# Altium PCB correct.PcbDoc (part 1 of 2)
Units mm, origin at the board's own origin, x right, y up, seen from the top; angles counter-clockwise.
Board outline 184.4 x 190.25 mm, 2 copper layers (Top Layer, Bottom Layer); 180 components, 157 nets, 610 pads, 206 vias.
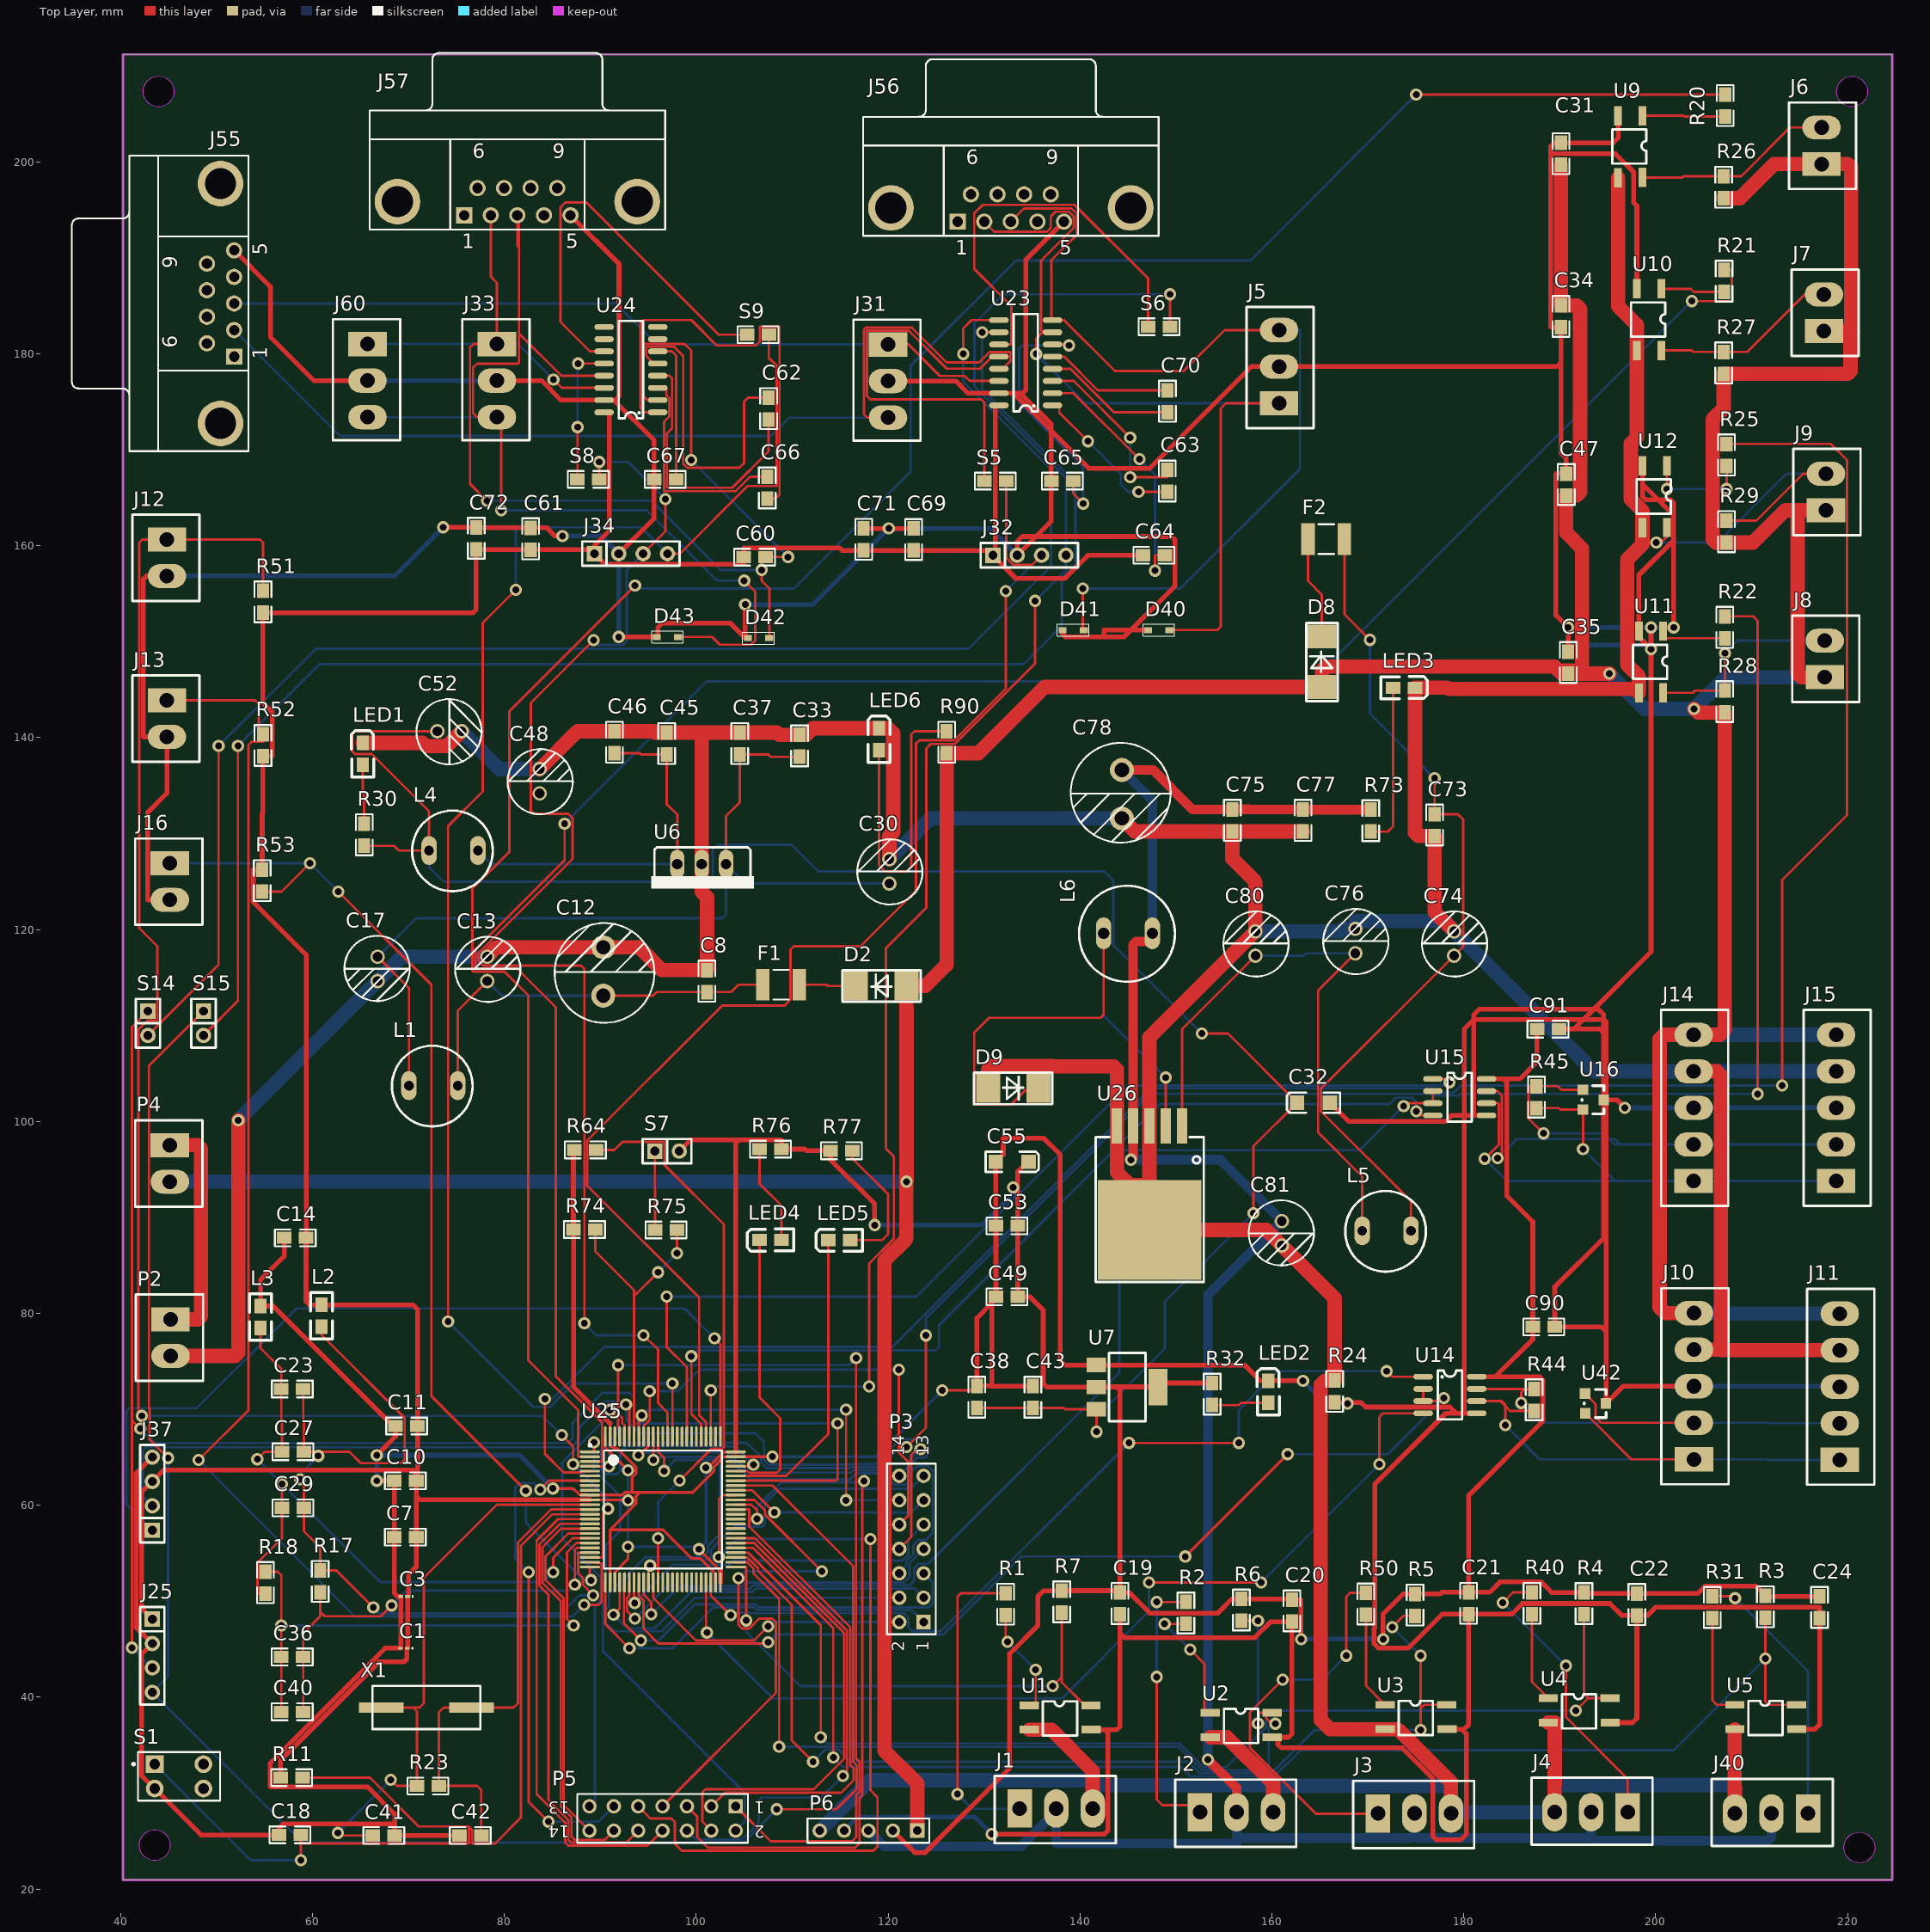
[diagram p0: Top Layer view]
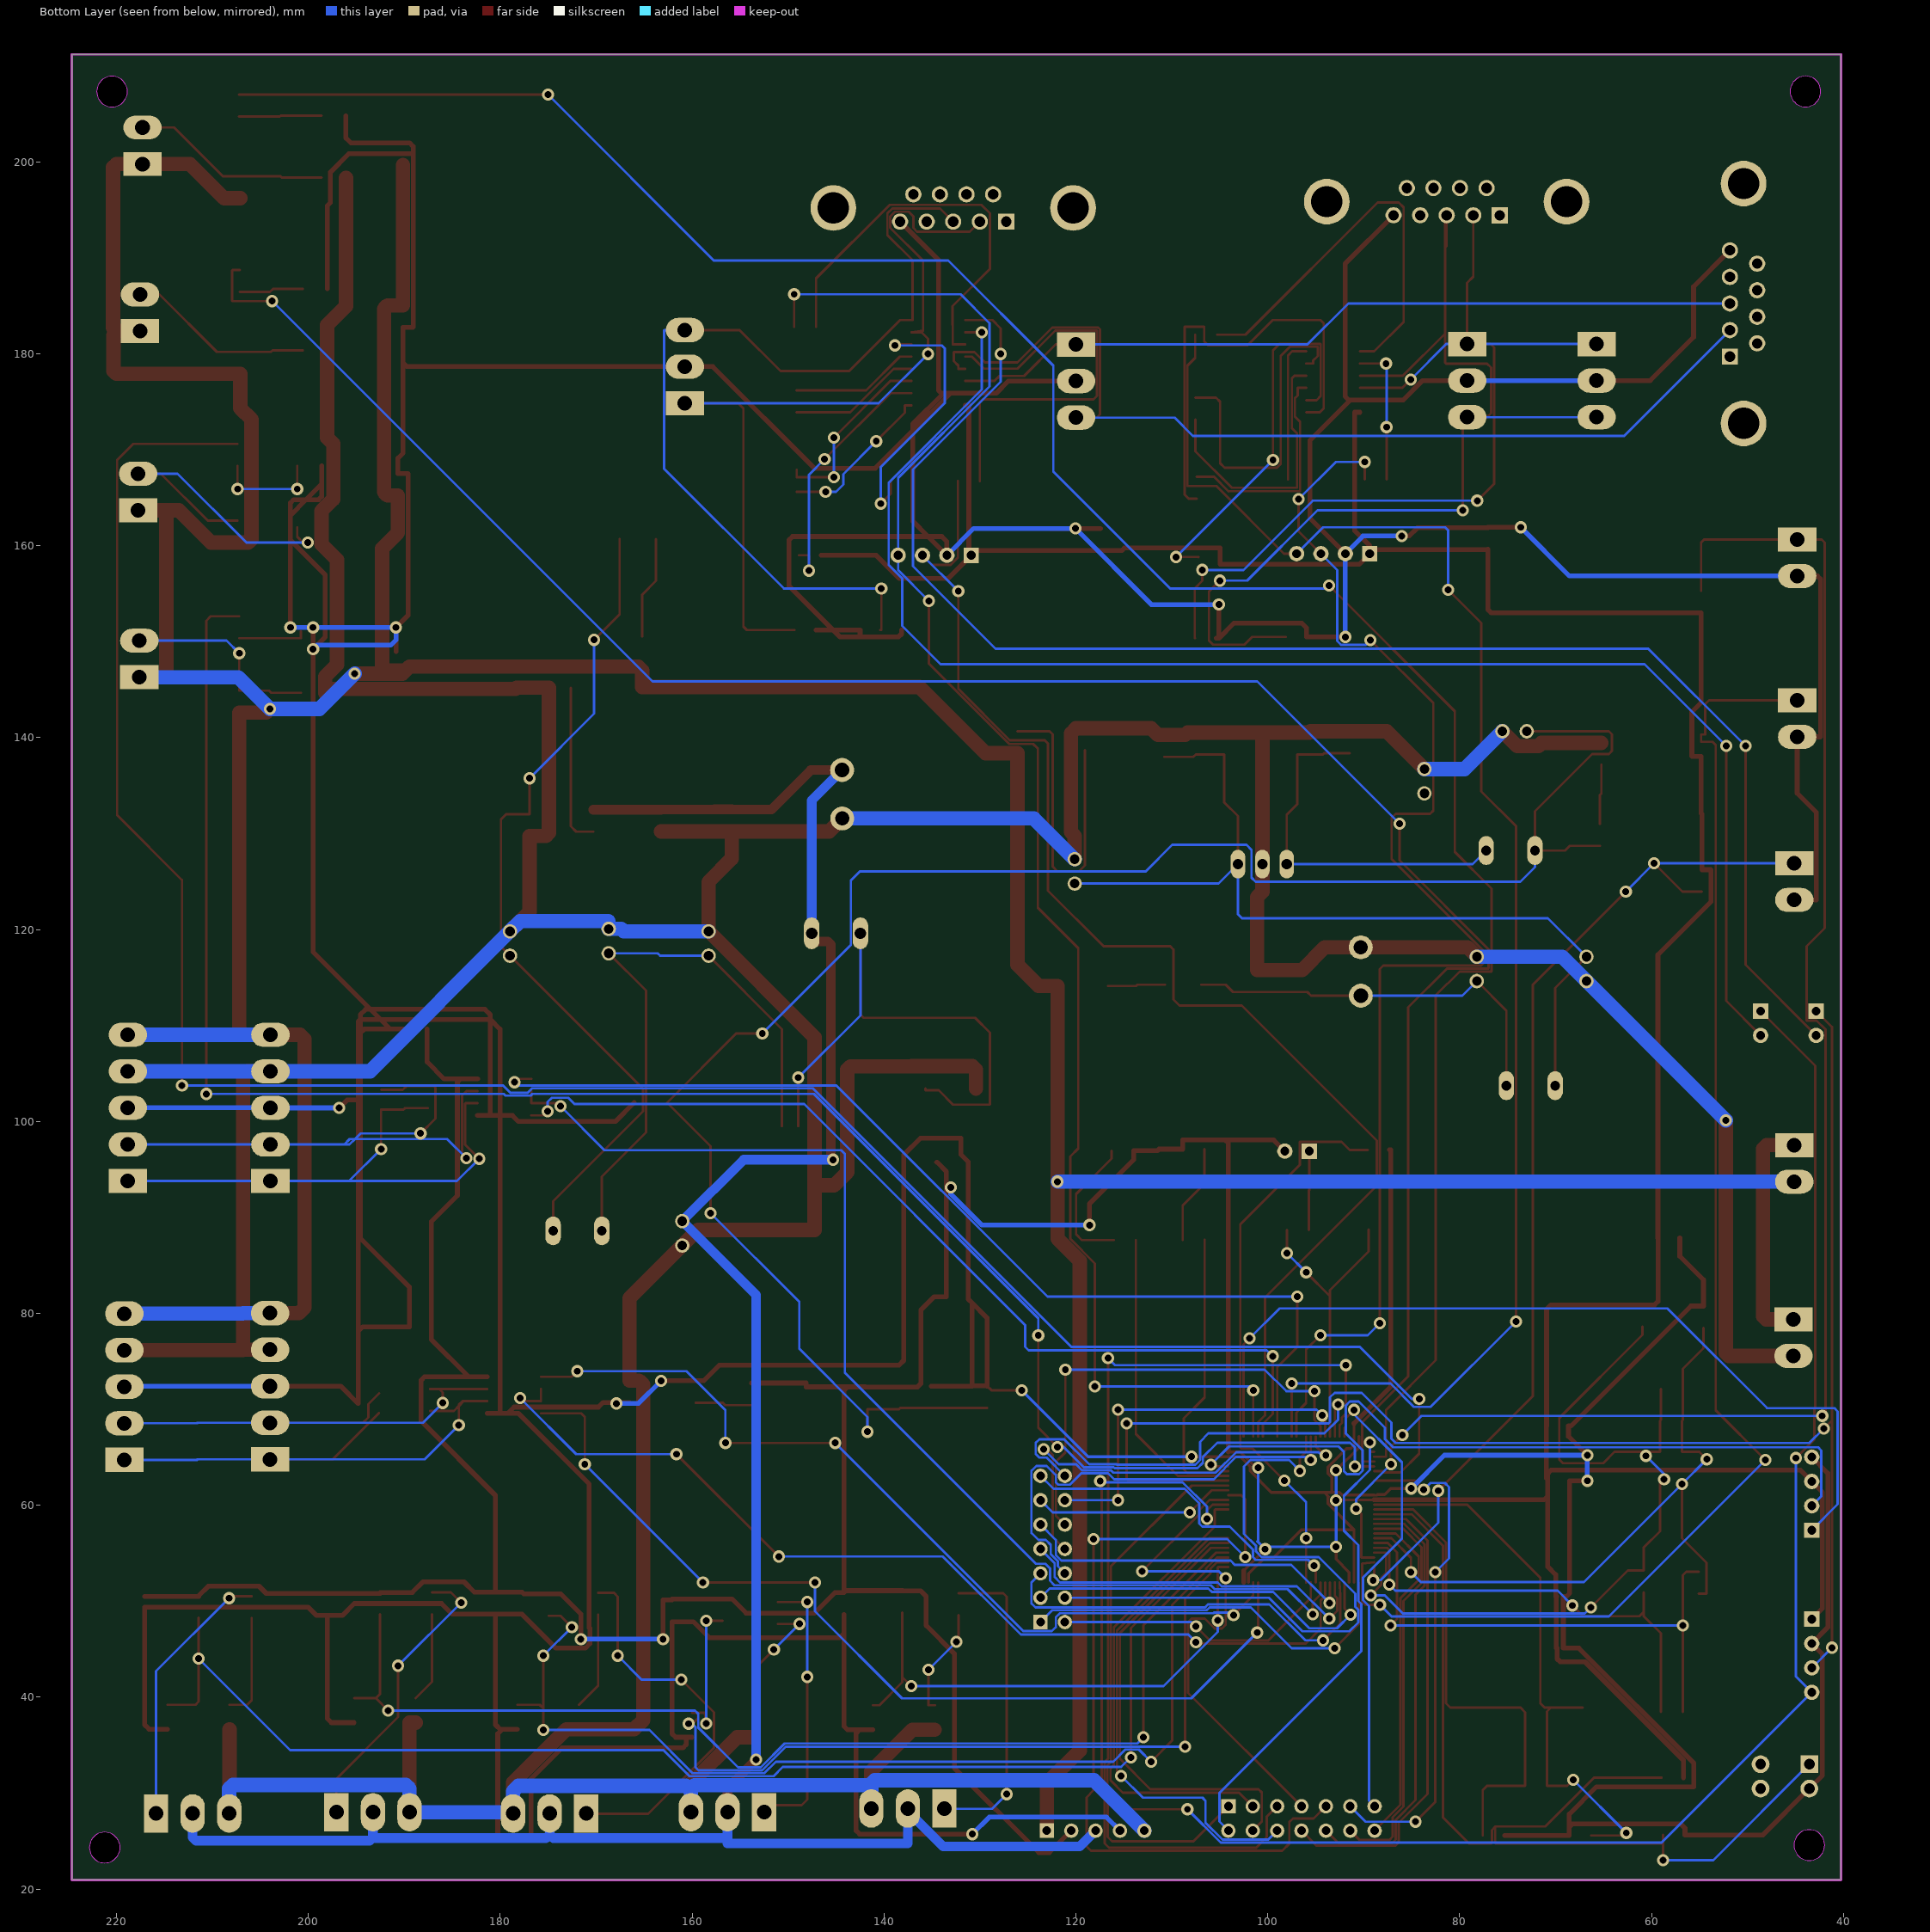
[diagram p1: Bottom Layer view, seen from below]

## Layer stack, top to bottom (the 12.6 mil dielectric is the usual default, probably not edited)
Top Solder: solder mask 0.0102, Solder Resist, Dk 3.5
Top Layer: signal copper 0.0356
Dielectric 1: dielectric 0.32, FR-4, Dk 4.8
Bottom Layer: signal copper 0.0356
Bottom Solder: solder mask 0.0102, Solder Resist, Dk 3.5

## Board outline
40.259,20.955 40.259,70.231 40.259,164.211 40.259,211.201 224.663,211.201 224.663,20.955
cut-out: 43.561,22.987 cw(c43.561,24.587) 41.961,24.587 cw(c43.561,24.587) 43.561,26.187 cw(c43.561,24.587) 45.161,24.587 cw(c43.561,24.587)
cut-out: 221.234,22.733 cw(c221.234,24.333) 219.634,24.333 cw(c221.234,24.333) 221.234,25.933 cw(c221.234,24.333) 222.834,24.333 cw(c221.234,24.333)
cut-out: 220.472,205.731 cw(c220.472,207.331) 218.872,207.331 cw(c220.472,207.331) 220.472,208.931 cw(c220.472,207.331) 222.072,207.331 cw(c220.472,207.331)
cut-out: 43.965,205.745 cw(c43.965,207.345) 42.365,207.345 cw(c43.965,207.345) 43.965,208.945 cw(c43.965,207.345) 45.565,207.345 cw(c43.965,207.345)

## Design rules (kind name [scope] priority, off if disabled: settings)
Clearance [All] p1: gap=0.051 ignorepadtopadclearanceinfootprint=FALSE except(0: Arc-Hole Track-Hole SMDPad-Hole THPad-Hole Via-Hole Fill-Hole Poly-Hole Region-Hole Text-Hole)
PolygonConnect [All] p1: connectstyle=Relief reliefconductorwidth=0.254 reliefentries=4 polygonreliefangle="90 Angle" airgapwidth=0.254
RoutingVias [All] p1: holewidth=0.711 width=1.27 viastyle="Through Hole" minholewidth=0.711 minwidth=1.27 maxholewidth=0.711 maxwidth=1.27
SolderMaskExpansion [All] p1: expansion=0.102
Width [All] p1: maxlimit=1.5 minlimit=0.254 preferedwidth=0.254 minimp=50.000000 maximp=50.000000 favimp=50.000000
30 further rules are at their usual default settings.

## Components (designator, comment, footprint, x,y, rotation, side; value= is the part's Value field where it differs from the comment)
C1 "10uf/50V 5%" 0603 69.523,45.103 r180 top
C3 "100nf/50V 5%" 0603 69.554,50.488 r180 top
C7 "100nf/50V 5%" 0805C 70.776,56.703 r180 top
C8 "100nf/50V 5%" 0805C 101.143,113.537 r90 top
C10 "100nf/50V 5%" 0805C 70.776,62.571 r180 top
C11 "100nf/50V 5%" 0805C 70.903,68.286 r180 top
C12 "220uf/35V" C10-35V330uf 90.312,113.108 r90 top
C13 "10uf/35V" C6.5-35V47uf 78.222,114.632 r90 top
C14 "100nf/50V 5%" 0805C 59.294,87.896 r180 top
C17 "220uf/35V" C6.5-35V47uf 66.792,117.172 r270 top
C18 "100nf/50V 5%" 0805C 56.571,25.63 r0 top
C19 "100nf/50V 5%" 0805C 144.19,48.683 r90 top
C20 "100nf/50V 5%" 0805C 162.115,47.915 r90 top
C21 "100nf/50V 5%" 0805C 180.53,48.7 r90 top
C22 "100nf/50V 5%" 0805C 198.056,48.573 r90 top
C23 "10uF/16V" 0805C 58.992,72.148 r180 top
C24 "100nf/50V 5%" 0805C 217.106,48.271 r90 top
C27 "100nf/50V 5%" 0805C 56.881,65.552 r0 top
C29 "10nf/50V 5%" 0805C 56.881,59.71 r0 top
C30 "47uf 50V" C6.5-35V47uf 120.132,124.792 r90 top
C31 "100nf/50V 5%" 0805C 190.119,201.938 r270 top
C32 "16V10uf" 1206-2 164.34,101.956 r180 top
C33 "100nf/50V 5%" 0805C 110.796,138.048 r90 top
C34 "100nf/50V 5%" 0805C 190.155,182.809 r90 top
C35 "100nf/50V 5%" 0805C 190.863,148.916 r270 top
C36 "10uf/50V 5%" 0805C 56.802,44.172 r0 top
C37 "10nf/50V 5%" 0805C 104.555,138.302 r90 top
C38 "100nf/50V 5%" 0805C 129.277,70.183 r90 top
C40 "10nf/50V 5%" 0805C 56.802,38.457 r0 top
C41 "20pF/50V 5%" 0805C 68.532,25.603 r180 top
C42 "20pF/50V 5%" 0805C 75.359,25.567 r0 top
C43 "10nf/50V 5%" 0805C 135.119,70.183 r90 top
C45 "10nf/50V 5%" 0805C 96.953,138.302 r90 top
C46 "100nf/50V 5%" 0805C 91.492,138.429 r90 top
C47 "100nf/50V 5%" 0805C 190.66,167.473 r270 top
C48 "47uf 50V" C6.5-35V47uf 83.683,134.19 r90 top
C49 "100nf/50V 5%" 0805C 133.468,81.74 r180 top
C52 "10uf 50V" C6.5-35V47uf 73.015,140.667 r0 top
C53 "10nf/50V 5%" 0805C 133.468,89.15 r180 top
C55 "16V10uf" 1206-2 132.931,95.783 r0 top
C60 "100nf/50V 5%" 0805C 105.006,158.794 r0 top
C61 "10uf/50V 5%" 0805C 82.761,159.638 r90 top
C62 "100nf/50V 5%" 0805C 107.528,175.383 r270 top
C63 "100nf/50V 5%" 0805C 149.119,165.656 r90 top
C64 "100nf/50V 5%" 0805C 146.609,158.986 r0 top
C65 "100nf/50V 5%" 0805C 139.248,166.769 r180 top
C66 "100nf/50V 5%" 0805C 107.437,164.938 r90 top
C67 "100nf/50V 5%" 0805C 97.846,166.94 r180 top
C69 "10uf/50V 5%" 0805C 122.677,159.56 r90 top
C70 "100nf/50V 5%" 0805C 149.101,176.149 r270 top
C71 "100nf/50V 5%" 0805C 117.434,161.75 r270 top
C72 "100nf/50V 5%" 0805C 77.048,161.873 r270 top
C73 "100nf/50V 5%" 0805C 176.942,131.982 r270 top
C74 "10uf/35V" C6.5-35V47uf 178.992,117.275 r90 top
C75 "10nf/50V 5%" 0805C 155.86,132.467 r270 top
C76 "220uf/35V" C6.5-35V47uf 168.705,117.529 r90 top
C77 "100nf/50V 5%" 0805C 163.226,132.467 r270 top
C78 "470u/16V" C10-35V330uf 144.371,136.625 r270 top
C80 "10u/35V" C6.5-35V47uf 158.291,117.275 r90 top
C81 "100uf/16V" C6.5-35V47uf 161.038,89.614 r270 top
C90 "100nf/50V 5%" 0805C 189.438,78.623 r180 top
C91 "100nf/50V 5%" 0805C 189.867,109.644 r180 top
D2 "1N5822" SS34 117.166,113.683 r270 top
D8 "1N5822" SS34 164.774,150.028 r180 top
D9 "1N5822" SS34 135.174,103.882 r90 top
D40 "SD12C" SD12C 148.219,151.213 r0 top
D41 "SD12C" SD12C 139.296,151.213 r0 top
D42 "SD12C" SD12C 106.497,150.368 r0 top
D43 "SD12C" SD12C 97.005,150.495 r0 top
F1 "500mA" 1812 108.829,114.251 r180 top
F2 "500mA" 1812 165.668,160.696 r0 top
J1 "CON3" CON-3P-3.81 133.738,28.37 r0 top
J2 "CON3" CON-3P-3.81 152.534,27.989 r0 top
J3 "CON3" CON-3P-3.81 171.076,27.862 r0 top
J4 "CON3" CON-3P-3.81 197.06,28.04 r180 top
J5 "CON3" CON-3P-3.81 160.782,174.879 r90 top
J6 "红色" CON-2P-3.81 217.297,199.779 r90 top
J7 "绿色" CON-2P-3.81 217.551,182.38 r90 top
J8 "黄色" CON-2P-3.81 217.627,146.297 r90 top
J9 "蓝色" CON-2P-3.81 217.754,163.696 r90 top
J10 "Header 5" CON-5P-3.81 203.996,64.838 r90 top
J11 "Header 5" CON-5P-3.81 219.19,64.788 r90 top
J12 "蓝色按键" CON-2P-3.81 44.831,160.655 r270 top
J13 "绿色按键" CON-2P-3.81 44.831,143.891 r270 top
J14 "Header 5" CON-5P-3.81 203.962,93.845 r90 top
J15 "Header 5" CON-5P-3.81 218.821,93.845 r90 top
J16 "绿色按键" CON-2P-3.81 45.136,126.899 r270 top
J25 "TTL" SIP4 43.307,44.323 r270 top
J31 "CON3" CON-3P-3.81 119.967,180.95 r270 top
J32 "USART4" SIP4 134.724,159.004 r0 top
J33 "CON3" CON-3P-3.81 79.2,180.994 r270 top
J34 "USART4" SIP4 93.195,159.175 r0 top
J37 "SWD" SIP4 43.307,61.214 r90 top
J40 "CON3" CON-3P-3.81 215.856,27.913 r180 top
J55 "D Connector 9" DSUB1.385-2H9 40.919,185.244 r90 top
J56 "D Connector 9" DSUB1.385-2H9 132.793,204.699 r0 top
J57 "D Connector 9" DSUB1.385-2H9 81.358,205.359 r0 top
J60 "CON3" CON-3P-3.81 65.712,180.994 r270 top
L1 "Inductor" LC-8.2 75.102,103.713 r180 top value="10uH 2A"
L2 "10uH" 0805 60.945,79.75 r270 top
L3 "10uH" 0805 54.595,79.623 r270 top
L4 "10uH 2A" LC-8.2 77.206,128.221 r180 top
L5 "Inductor" LC-8.2 174.466,88.581 r180 top value="10uH 2A"
L6 "331" LC-10 145.429,119.336 r180 top
LED1 "LED R" 0805D 65.268,137.238 r90 top
LED2 "LED B" 0805D 159.654,70.77 r90 top
LED3 "LED G" 0805D 172.727,145.178 r0 top
LED4 "LED R" 0805D 108.796,87.681 r180 top
LED5 "LED B" 0805D 115.965,87.657 r180 top
LED6 "LED B" 0805D 119.093,138.762 r90 top
P2 "Power24V" CON-2P-3.81 45.212,79.375 r270 top
P3 "Header 7X2" HDR2X7 123.701,47.829 r90 top
P4 "Power24V" CON-2P-3.81 45.136,97.536 r270 top
P5 "Header 7X2" HDR2X7 104.111,28.633 r180 top
P6 "Header 5" HDR1X5 123.034,26.093 r180 top
R1 "620R 1%" 0805R 132.295,48.579 r90 top
R2 "620R 1%" 0805R 151.091,47.659 r90 top
R3 "2K 1%" 0805R 211.479,48.307 r90 top
R4 "2K 1%" 0805R 192.577,48.652 r90 top
R5 "2K 1%" 0805R 174.967,48.5 r90 top
R6 "2K 1%" 0805R 156.869,47.977 r90 top
R7 "2K 1%" 0805R 138.137,48.833 r90 top
R11 "10k 1%" 0805R 58.938,31.66 r180 top
R17 "10R" 0805R 60.861,50.944 r90 top
R18 "10R" 0805R 55.06,53.057 r270 top
R20 "620R 1%" 0805R 207.289,204.755 r90 top
R21 "620R 1%" 0805R 207.18,186.467 r90 top
R22 "620R 1%" 0805R 207.256,150.384 r90 top
R23 "1M" 0805R 73.152,30.792 r180 top
R24 "0R 1%" 0805R 166.499,72.977 r270 top
R25 "620R 1%" 0805R 207.434,168.35 r90 top
R26 "2K 1%" 0805R 207.137,196.246 r90 top
R27 "2K 1%" 0805R 207.137,177.935 r90 top
R28 "2K 1%" 0805R 207.256,142.637 r90 top
R29 "2K 1%" 0805R 207.434,160.349 r90 top
R30 "10k 1%" 0805R 65.352,130.992 r270 top
R31 "620R 1%" 0805R 205.955,48.246 r90 top
R32 "10K 1%" 0805R 153.831,70.46 r90 top
R40 "620R 1%" 0805R 187.159,48.675 r90 top
R44 "120R 1%" 0805R 187.284,72.105 r270 top
R45 "120R 1%" 0805R 187.538,103.652 r270 top
R50 "620R 1%" 0805R 169.844,48.604 r90 top
R51 "2K 1%" 0805R 54.889,153.035 r90 top
R52 "2K 1%" 0805R 54.889,138.072 r90 top
R53 "2K 1%" 0805R 54.719,126.215 r270 top
R64 "10K 1%" 0805R 87.332,96.99 r0 top
R73 "10K 1%" 0805R 170.356,130.229 r90 top value=10K
R74 "10K 1%" 0805R 89.468,88.778 r180 top
R75 "1K 1%" 0805R 97.977,88.735 r180 top
R76 "10K 1%" 0805R 106.629,97.072 r0 top
R77 "10K 1%" 0805R 116.254,96.994 r180 top
R90 "47K 1%" 0805R 126.058,140.644 r270 top
S1 "SW-PB" DPST-4 46.101,31.75 r0 top
S5 "0R 1%" 0805R 132.288,166.794 r180 top
S6 "0R 1%" 0805R 149.355,182.88 r180 top
S7 "SW SPST" SIP2 96.961,96.906 r0 top
S8 "0R 1%" 0805R 89.87,166.965 r180 top
S9 "0R 1%" 0805R 107.546,182.035 r180 top
S14 "KEY-9" SIP2 42.85,110.236 r270 top
S15 "KEY-9" SIP2 48.641,110.236 r270 top
U1 "TLP181" TLP-181 134.716,39.158 r0 top
U2 "TLP181" TLP-181 153.588,38.365 r0 top
U3 "TLP181" TLP-181 171.8,39.206 r0 top
U4 "TLP181" TLP-181 188.818,39.889 r0 top
U5 "TLP181" TLP-181 208.249,39.206 r0 top
U6 "ZLG K7805-500" TO-220 99.764,126.849 r180 top
U7 "LM1117-3.3" SOT-223 144.655,71.961 r270 top
U9 "TLP181" TLP-181 198.628,204.809 r270 top
U10 "TLP181" TLP-181 200.584,186.775 r270 top
U11 "TLP181" TLP-181 200.787,151.1 r270 top
U12 "TLP181" TLP-181 201.168,168.327 r270 top
U14 "SP3485" SO-8 178.564,71.493 r0 top
U15 "SP3485" SO-8 179.58,102.532 r0 top
U16 "SM712" SM712 191.663,104.362 r270 top
U23 "MAX3232" SO-16 134.343,179.07 r180 top
U24 "MAX3232" SO-16 93.195,178.352 r180 top
U25 "STM32F103VCT6" LQFP100 96.52,59.563 r0 top
U26 "LM2596-5" TO-263-5 147.219,89.16 r180 top
U42 "SM712" SM712 191.897,72.722 r270 top
X1 "8M" CRYSTAL-T 71.882,38.92 r0 top

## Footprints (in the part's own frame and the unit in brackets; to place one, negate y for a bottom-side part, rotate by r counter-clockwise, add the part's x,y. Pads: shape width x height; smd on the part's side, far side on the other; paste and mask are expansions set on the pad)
0603 [mm] "Chip Inductor, Body 0.6x0.3mm, IPC High Density"
  rect 0.5x0.3 smd: 1(-0.35,0) 2(0.35,0)
  silkscreen extent -0.9,-0.05 -0.9,0.05, body extent -0.33,-0.18 0.33,0.18, height 0.55
0805 [mil]
  rect 60x50 smd: 1(-45,0) 2(45,0)
  silkscreen extent -95,-45 95,45
0805C [mil]
  rect 60x50 smd: 1(-1.89,0.71) 2(88.11,0.71)
  silkscreen extent -41,-34 127,35
0805D [mil]
  rect 60x50 smd: 1(-3.11,0.95) 2(86.89,0.95)
  silkscreen extent -53,-44 137,47
0805R [mil]
  rect 60x50 smd: 1(-0.9,1.69) 2(89.1,1.69)
  silkscreen extent -40,-33 128,36
1206-2 [mm]
  rect 1.5x1.5 smd: 1(1.714,0) 2(-1.715,0)
  silkscreen extent -2.76,-1.05 2.76,1.05
1812 [mm] "Chip Capacitor, Body 4.5x3.2mm, IPC High Density"
  rect 1.4x3.3 smd: 1(-1.9,0) 2(1.9,0)
  silkscreen extent -0.8,-1.55 0.8,1.55, body extent -2.4,-1.7 2.4,1.7, height 1.4
C6.5-35V47uf [mm]
  round 1.5 hole 1: 1(0,0) 2(2.54,0)
  silkscreen extent -2.18,-3.45 4.62,3.35
C10-35V330uf [mm]
  round 2.5 hole 1.5: 1(0,0) 2(5.044,-0.009)
  silkscreen extent -2.83,-5.33 7.57,5.07
CON-2P-3.81 [mm]
  rect 2.5x4 hole 1.524: 1(0,0)
  oval 2.5x4 hole 1.524: 2(3.81,0)
  silkscreen extent -2.59,-3.61 6.41,3.39
CON-3P-3.81 [mil]
  rect 100x157.48 hole 60: 1(-1,1)
  oval 100x157.48 hole 60: 2(149,1) 3(299,1)
  silkscreen extent -103,-141 394,135
CON-5P-3.81 [mil]
  rect 100x157.48 hole 60: 1(-2,0)
  oval 100x157.48 hole 60: 2(148,0) 3(298,0) 4(448,0) 5(598,0)
  silkscreen extent -104,-142 700,134
CRYSTAL-T [mm]
  rect 4.65x1.1 smd: 1(4.705,0) 2(-4.705,0)
  silkscreen extent -5.62,-2.24 5.63,2.26
DPST-4 [mm] "Switch; 4 Leads"
  rect 1.85x1.85 hole 1.1: 1(-2.54,1.27)
  round 1.85 hole 1.1: 2(-2.54,-1.27) 3(2.54,-1.27) 4(2.54,1.27)
  silkscreen extent -4.88,-2.54 4.28,2.54
DSUB1.385-2H9 [mm] "Connector; D Subminiature; 9 Position; Right Angle; Pitch 1.385 mm"
  rect 1.69x1.69 hole 1.09: 1(-5.54,-10.92)
  round 1.69 hole 1.09: 2(-2.77,-10.92) 3(0,-10.92) 4(2.77,-10.92) 5(5.54,-10.92) 6(-4.155,-8.08) 7(-1.385,-8.08) 8(1.385,-8.08) 9(4.155,-8.08)
  round 4.76 hole 3.26: 10(-12.495,-9.5) 11(12.495,-9.5)
  silkscreen extent -15.4,-12.4 15.4,6
HDR1X5 [mm] "Connector; Header; 5 Position"
  rect 1.5x1.5 hole 0.9: 1(0,0)
  round 1.5 hole 0.9: 2(2.54,0) 3(5.08,0) 4(7.62,0) 5(10.16,0)
  silkscreen extent -1.27,-1.27 11.43,1.27
HDR2X7 [mm] "Connector; Header; 7x2 Position"
  rect 1.5x1.5 hole 0.9: 1(0,0)
  round 1.5 hole 0.9: 2(0,2.54) 3(2.54,0) 4(2.54,2.54) 5(5.08,0) 6(5.08,2.54) 7(7.62,0) 8(7.62,2.54) 9(10.16,0) 10(10.16,2.54) 11(12.7,0) 12(12.7,2.54) 13(15.24,0) 14(15.24,2.54)
  silkscreen extent -1.27,-1.27 16.51,3.81
LC-8.2 [mm]
  oval 1.6x3 hole 1: 1(-0.034,-0.017) 2(5.046,-0.017)
  silkscreen extent -1.59,-4.17 6.81,4.22
LC-10 [mm]
  oval 1.6x3.3 hole 1.2: 1(-2.117,-0.271) 2(2.963,-0.271)
  silkscreen extent -4.47,-5.23 5.53,4.77
LQFP100 [mm]
  oval 2.1x0.3 smd: 1(-7.6,6) 2(-7.6,5.5) 3(-7.6,5) 4(-7.6,4.5) 5(-7.6,4) 6(-7.6,3.5) 7(-7.6,3) 8(-7.6,2.5) 9(-7.6,2) 10(-7.6,1.5) 11(-7.6,1) 12(-7.6,0.5) 13(-7.6,0) 14(-7.6,-0.5) 15(-7.6,-1) 16(-7.6,-1.5) 17(-7.6,-2) 18(-7.6,-2.5) 19(-7.6,-3) 20(-7.6,-3.5) 21(-7.6,-4) 22(-7.6,-4.5) 23(-7.6,-5) 24(-7.6,-5.5) 25(-7.6,-6) 51(7.6,-6) 52(7.6,-5.5) 53(7.6,-5) 54(7.6,-4.5) 55(7.6,-4) 56(7.6,-3.5) 57(7.6,-3) 58(7.6,-2.5) 59(7.6,-2) 60(7.6,-1.5) 61(7.6,-1) 62(7.6,-0.5) 63(7.6,0) 64(7.6,0.5) 65(7.6,1) 66(7.6,1.5) 67(7.6,2) 68(7.6,2.5) 69(7.6,3) 70(7.6,3.5) 71(7.6,4) 72(7.6,4.5) 73(7.6,5) 74(7.6,5.5) 75(7.6,6)
  oval 0.3x2.1 smd: 26(-6,-7.6) 27(-5.5,-7.6) 28(-5,-7.6) 29(-4.5,-7.6) 30(-4,-7.6) 31(-3.5,-7.6) 32(-3,-7.6) 33(-2.5,-7.6) 34(-2,-7.6) 35(-1.5,-7.6) 36(-1,-7.6) 37(-0.5,-7.6) 38(0,-7.6) 39(0.5,-7.6) 40(1,-7.6) 41(1.5,-7.6) 42(2,-7.6) 43(2.5,-7.6) 44(3,-7.6) 45(3.5,-7.6) 46(4,-7.6) 47(4.5,-7.6) 48(5,-7.6) 49(5.5,-7.6) 50(6,-7.6) 76(6,7.6) 77(5.5,7.6) 78(5,7.6) 79(4.5,7.6) 80(4,7.6) 81(3.5,7.6) 82(3,7.6) 83(2.5,7.6) 84(2,7.6) 85(1.5,7.6) 86(1,7.6) 87(0.5,7.6) 88(0,7.6) 89(-0.5,7.6) 90(-1,7.6) 91(-1.5,7.6) 92(-2,7.6) 93(-2.5,7.6) 94(-3,7.6) 95(-3.5,7.6) 96(-4,7.6) 97(-4.5,7.6) 98(-5,7.6) 99(-5.5,7.6) 100(-6,7.6)
  silkscreen extent -7.72,-6.15 6.15,6.82
SD12C [mm]
  rect 0.83x0.63 smd: 1(-1.11,0) 2(1.11,0)
  silkscreen extent -1.65,-0.63 1.65,0.64
SIP2 [mil]
  rect 63x63 hole 36: 1(-50,0)
  round 63 hole 36: 2(50,0)
  silkscreen extent -100,-50 100,50
SIP4 [mil]
  rect 63x63 hole 36: 1(-150,0)
  round 63 hole 36: 2(-50,0) 3(50,0) 4(150,0)
  silkscreen extent -200,-50 200,50
SM712 [mm]
  rect 1.1x1.1 smd: 1(1.068,0.743) 2(3.128,0.763) 3(2.118,2.923)
  silkscreen extent 0.65,0.66 3.57,2.95
SO-8 [mil]
  oval 80x24 smd: 1(-110,75) 2(-110,25) 3(-110,-25) 4(-110,-75) 5(110,-75) 6(110,-25) 7(110,25) 8(110,75)
  silkscreen extent -50,-100 50,100
SO-16 [mil]
  oval 80x24 smd: 1(-110,175) 2(-110,125) 3(-110,75) 4(-110,25) 5(-110,-25) 6(-110,-75) 7(-110,-125) 8(-110,-175) 9(110,-175) 10(110,-125) 11(110,-75) 12(110,-25) 13(110,25) 14(110,75) 15(110,125) 16(110,175)
  silkscreen extent -50,-200 50,200
SOT-223 [mil]
  rect 59x79 smd: 1(-104.55,-116.77) 2(-14,-116.77) 3(76.55,-116.77)
  rect 150x79 smd: 2(-14.67,136.77)
  silkscreen extent -154,-65 126,85
SS34 [mm]
  rect 3x2.5 smd: 1(-0.44,4.743) 2(-0.44,-0.517)
  silkscreen extent -2.08,-1.93 1.19,6.22
TLP-181 [mm]
  rect 2x0.8 smd: 1(0,0) 2(0,-2.54) 3(6.452,-2.54) 4(6.426,0)
  silkscreen extent 1.42,-3.15 4.98,0.41
TO-220 [mm]
  oval 1.5x3 hole 1.1: 1(-3.35,0.025) 2(-0.805,0.029) 3(1.735,0.029)
  silkscreen extent -6.27,-1.72 4.45,2.6
TO-263-5 [mm]
  rect 1.07x3.66 smd: 1(-3.425,-10.36) 2(-1.725,-10.36) 3(-0.025,-10.36) 4(1.675,-10.36) 5(3.375,-10.36)
  rect 10.8x10.41 smd: 3(-0.025,0.465)
  silkscreen extent -5.69,-9.21 5.59,5.89

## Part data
C1 C3 C7 C8 C10 C11 C14 C18 C19 C20 C21 C22 C24 C27 C29 C31 C33 C34 C35 C36 C37 C38 C40 C41 C42 C43 C45 C46 C47 C49 C53 C60 C61 C62 C63 C64 C65 C66 C67 C69 C70 C71 C72 C73 C75 C77 C90 C91: library part CAP, "Capacitor"
C12 C13 C17 C23 C30 C48 C52 C74 C76 C78 C80 C81: library part "CAPACITOR POL", "Capacitor"
C32 C55: library part CAP+
D2 D8 D9 D40 D41 D42 D43: library part DIODE, "Diode"
F1 F2: library part "Fuse 1", "Fuse"
J1 J2 J3 J4 J5 J31 J33 J40 J60: "Connector"
J6 J7 J8 J9 J12 J13 J16 P2 P4: library part CON2, "Connector"
J10 J11 J14 J15 P6: "Header, 5-Pin"
J25 J32 J34: library part CON4, "Connector"
J37: library part CON4, "5264,, 4-Pin"
J55 J56 J57: "Receptacle Assembly, 9 Position, Right Angle", PackageDocument=O
L2 L3: library part RES1
L4: library part INDUCTOR1
L6: library part INDUCTOR
LED1 LED2 LED3 LED4 LED5 LED6: library part LED
P3 P5: "Header, 7-Pin, Dual row"
R1 R2 R3 R4 R5 R6 R7 R11 R17 R18 R20 R21 R22 R23 R24 R25 R26 R27 R28 R29 R30 R31 R32 R40 R44 R45 R50 R51 R52 R53 R64 R74 R75 R76 R77 R90: library part RES2
R73: library part Res1, "Resistor"
S1: "Switch"
S5 S6 S8 S9: library part RES
S14 S15: library part KEY-2
U1 U2 U3 U4 U5 U9 U10 U11 U12: library part TLP521-1
U6: library part VOLTREG
U7: library part LM1117
U14 U15: library part MAX485
U26: library part LM2596-5.0
X1: library part CRYSTAL

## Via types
v1: diameter 1.27, hole 0.711, Top Layer to Bottom Layer, 206 vias

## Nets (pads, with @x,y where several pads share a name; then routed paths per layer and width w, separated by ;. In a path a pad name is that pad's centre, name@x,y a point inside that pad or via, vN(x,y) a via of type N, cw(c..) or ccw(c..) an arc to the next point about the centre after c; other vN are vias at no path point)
3V3: C1.1 C3.1 C7.1 C10.1 C11.1 C14.1 C19.2 C20.2 C21.2 C22.2 C24.2 C49.1 C53.1 C55.1 C60.1 C61.1 C64.1 C69.1 C71.2 C72.2 C90.2 C91.2 J25.1 J32.1 J34.1 J37.3 L2.1 P6.2 R3.2 R4.2 R5.2 R6.2 R7.2 R11.2 R32.2 R51.1 R52.1 R53.1 R76.2 R77.2 S7.2 U7.2 U14.8 U15.8 U23.16 U24.16 U25.11 U25.28 U25.50 U25.75 U25.100 | length 735.7
  Top Layer w0.254: C55.1@134.484,95.754 134.645,95.754 C55.1@134.645,95.783 ; U7.2@141.689,72.317 141.935,72.317 143.827,72.317
  Top Layer w0.3: U25.11@88.92,60.563 v1@92.828,60.563 ; U25.100@90.52,67.163 90.52,66.02 v1(92.888,63.652) ; U25.28@91.52,51.963 91.52,53.023 92.888,54.39 v1(92.888,55.677) ; v1(100.277,55.425) 102.52,53.182 ; v1(101.016,63.906) 101.213,63.906 102.87,65.563 U25.75@104.115,65.563
  Top Layer w0.5: J25.1@43.307,48.133 42.189,49.251 42.189,61.366 J37.3@43.307,62.484 44.475,63.652 70.485,63.652 70.824,63.313 C10.1@70.824,62.687 ; R11.2@56.675,31.617 56.675,33.426 66.937,43.688 69.532,43.688 69.85,44.005 69.85,45.103 C1.1@69.873,45.103 69.926,45.103 C3.1@69.926,50.488 ; C3.1@69.904,50.488 C3.1@69.926,50.488 ; C72.2@77.066,159.635 C72.2@77.066,159.59 ; U25.11@88.92,60.563 88.918,60.561 71.223,60.561 70.824,60.96 ; U24.16@90.401,173.907 90.957,173.907 90.957,161.582 89.385,160.01 J34.1@89.385,159.175 ; v1@92.828,60.563 v1(92.888,60.503) ; S7.2@98.231,96.906 99.395,98.069 104.457,98.069 ; U25.50@102.52,51.963 102.52,53.182 ; U25.75@104.12,65.563 104.115,65.563 104.115,97.727 104.457,98.069 ; v1(118.593,89.205) 118.593,91.411 113.991,96.012 R77.2@113.991,96.951 111.507,96.951 111.342,97.115 R76.2@108.892,97.115 108.892,98.044 108.867,98.069 104.457,98.069 ; P6.2@120.494,26.093 122.775,23.812 123.867,23.812 132.664,32.609 132.664,44.526 135.611,47.473 135.611,50.499 136.207,51.096 R7.2@138.094,51.096 138.094,51.105 C19.2@144.172,51.105 ; U23.16@131.549,174.625 131.166,174.625 131.166,159.004 J32.1@130.914,159.004 ; v1(133.045,93.142) 133.516,93.613 ; C55.1@134.484,95.754 133.516,94.786 133.516,93.613 ; 143.827,72.317 144.172,71.972 C19.2@144.172,51.105 ; C64.1@146.561,159.004 140.818,159.004 138.405,156.591 133.327,156.591 J32.1@130.914,159.004 ; U7.2@148.129,72.334 U7.2@148.129,72.339 ; R32.2@153.788,72.723 153.788,72.746 148.129,72.746 U7.2@148.129,72.339 ; v1(163.043,46.05) 163.043,50.127 163.017,50.153 C20.2@162.097,50.153 162.097,50.24 R6.2@156.826,50.24 155.853,50.24 154.381,48.768 147.263,48.768 145.11,50.921 C19.2@144.172,50.921 C19.2@144.172,51.105 ; v1(171.602,46.05) 171.602,48.68 173.685,50.763 R5.2@174.924,50.763 177.549,50.763 177.724,50.938 C21.2@180.512,50.938 ; U14.8@181.358,73.398 183.306,73.398 ; U15.8@182.374,104.437 184.15,104.437 ; C91.2@187.629,109.626 187.629,106.214 185.852,104.437 184.15,104.437 ; C24.2@217.088,50.509 211.436,50.509 R3.2@211.436,50.57 210.434,51.571 205.153,51.571 204.392,50.811 C22.2@198.038,50.811 192.534,50.811 R4.2@192.534,50.915 189.166,50.915 188.062,52.019 183.784,52.019 182.702,50.938 C21.2@180.512,50.938 ; C3.1@69.926,50.488 70.002,50.488 70.002,52.772 70.824,53.594 C7.1@70.824,56.685 70.824,60.96 ; 70.824,60.96 C10.1@70.824,62.553 C10.1@70.824,62.687 ; C10.1@70.824,62.687 70.968,62.83 70.968,68.268 C11.1@70.951,68.268 70.951,80.426 70.485,80.893 L2.1@60.945,80.893 59.69,80.893 59.334,81.248 59.334,87.878 C14.1@59.342,87.878 59.342,117.365 53.823,122.885 53.823,126.213 53.848,126.238 R53.1@54.762,126.238 54.762,132.047 54.846,132.131 R52.1@54.846,138.049 55.778,138.049 55.804,138.074 55.804,142.672 54.846,143.629 R51.1@54.846,153.012 76.726,153.012 77.066,153.352 C72.2@77.066,159.59 ; C72.2@77.066,159.59 C61.1@82.743,159.59 88.97,159.59 J34.1@89.385,159.175 ; J34.1@89.385,159.175 90.496,158.064 104.933,158.064 104.958,158.09 C60.1@104.958,158.812 104.958,159.741 104.984,159.766 114.96,159.766 115.214,159.512 C71.2@117.452,159.512 C69.1@122.659,159.512 130.406,159.512 J32.1@130.914,159.004 ; 133.516,93.613 C53.1@133.516,89.132 133.502,89.132 133.502,81.722 C49.1@133.516,81.722 134.788,81.722 136.169,80.34 136.169,72.672 136.525,72.317 U7.2@141.689,72.317 141.935,72.317 141.958,72.339 U7.2@148.129,72.339 ; C21.2@180.512,50.938 180.512,61.031 188.265,68.783 188.265,73.025 187.892,73.398 183.306,73.398 ; 183.306,73.398 187.2,77.292 C90.2@187.2,78.605 187.2,89.558 184.48,92.278 184.48,104.107 184.15,104.437
  Bottom Layer w0.3: v1(92.888,63.652) v1(92.888,60.503) v1(92.888,55.677) 100.025,55.677 v1(100.277,55.425) 101.092,56.24 101.016,56.316 v1(101.016,63.906)
  Bottom Layer w0.5: v1(118.593,89.205) 129.819,89.205 133.045,92.431 v1(133.045,93.142) ; v1(163.043,46.05) v1(171.602,46.05)
5V: C75.1 C77.1 C78.1 C81.1 J1.2 J2.2 J3.2 J4.2 J40.2 L6.1 P6.3 R73.2 U26.4 | length 267.3
  Top Layer w1: C78.1@144.371,136.625 147.626,136.625 151.736,132.515 C75.1@155.878,132.515 155.878,132.537 157.683,132.537 157.705,132.515 C77.1@163.244,132.515 163.244,132.492 R73.2@170.313,132.492 ; v1(145.313,96.012) 145.544,96.243 U26.4@145.544,99.52 145.544,118.427 145.861,118.745 147.546,118.745 L6.1@147.546,119.607 ; v1(153.34,33.503) 156.318,30.524 J2.2@156.318,28.015
  Bottom Layer w1: P6.3@117.954,26.093 119.613,24.435 133.833,24.435 J1.2@137.522,28.125 ; J1.2@137.522,28.396 J1.2@137.522,28.125 ; C78.1@144.371,136.625 147.546,133.45 L6.1@147.546,119.607 ; v1(145.313,96.012) 154.64,96.012 C81.1@161.038,89.614 153.34,81.916 v1(153.34,33.503) ; J2.2@156.318,28.015 156.318,25.717 ; J3.2@174.86,27.888 174.86,25.717 ; J4.2@193.275,28.015 193.275,25.451 ; J40.2@212.071,27.888 212.071,25.4 211.716,25.044 193.631,25.044 193.275,25.4 193.275,25.451 ; J1.2@137.522,28.125 137.522,24.765 156.318,24.765 156.318,25.717 ; 156.318,25.717 156.712,25.324 174.467,25.324 174.86,25.717 ; 174.86,25.717 175.254,25.324 193.148,25.324 193.275,25.451
24V: C31.2 C34.2 C35.2 C47.2 D2.1 D8.1 J6.1 J7.1 J8.1 J9.1 J10.5 J11.5 J14.5 J15.5 P4.2 P6.1 R26.1 R27.1 R28.1 R29.1 R90.2 | length 579.7
  Top Layer w1.5: v1(121.92,93.726) 121.92,111.887 121.91,111.897 ; P6.1@123.034,26.093 123.034,31.017 119.609,34.442 119.609,85.471 121.91,87.772 121.91,111.897 ; C31.2@190.137,199.7 C34.2@190.137,185.047 191.77,185.047 192.126,184.692 192.126,165.591 191.77,165.235 C47.2@190.678,165.235 190.678,161.366 192.329,159.715 192.329,147.002 190.202,147.002 190.202,146.678 ; v1(195.174,146.678) C35.2@190.881,146.678 190.202,146.678 ; J10.5@203.996,80.027 200.977,80.027 200.406,80.599 200.406,108.585 200.855,109.034 J14.5@203.962,109.034 206.71,109.034 207.213,109.537 R28.1@207.213,142.614 204.401,142.614 v1(204.013,143.002) ; R26.1@207.094,196.223 208.788,196.223 212.344,199.779 J6.1@217.297,199.779 220.028,199.779 220.37,199.437 220.37,182.723 220.028,182.38 219.867,182.38 ; J7.1@217.551,182.38 219.867,182.38 ; J8.1@217.627,146.297 215.196,146.297 214.808,146.685 214.808,163.696 ; J9.1@217.754,163.696 214.808,163.696 ; 121.91,111.897 D2.1@121.91,114.124 123.901,114.124 126.101,116.323 R90.2@126.101,138.381 129.413,138.381 136.317,145.285 D8.1@165.215,145.285 165.215,147.002 165.608,147.396 189.484,147.396 190.202,146.678 ; 214.808,163.696 213.512,163.696 210.143,160.326 R29.1@207.391,160.326 206.272,160.326 205.943,160.655 205.943,173.177 207.094,174.328 R27.1@207.094,177.912 220.028,177.912 220.32,178.205 220.32,181.927 219.867,182.38
  Bottom Layer w1.5: P4.2@45.136,93.726 v1(121.92,93.726) ; v1(195.174,146.678) 198.85,143.002 v1(204.013,143.002) 207.308,146.297 J8.1@217.627,146.297 ; J14.5@203.962,109.034 J15.5@218.821,109.034 ; J10.5@203.996,80.027 206.815,80.027 206.865,79.978 J11.5@219.19,79.978
232_Rxd2: D43.2 J33.3 J57.3 J60.3 U24.13 | length 109.3
  Top Layer w0.254: v1(79.68,163.703) 79.68,173.399 J33.3@79.225,173.399 77.153,173.399 76.743,173.809 76.743,178.552 77.153,178.962 81.426,178.962 81.534,179.07 81.534,182.118 ; U24.13@90.401,177.717 85.935,177.717 81.534,182.118 ; D43.2@98.115,150.495 101.651,150.495 102.451,149.695 105.727,149.695 106.147,150.114 106.147,155.219 v1(105.004,156.362) ; 81.534,182.118 81.534,191.084 ; 81.534,191.084 81.534,194.439 J57.3@81.358,194.439 81.358,191.26 81.534,191.084
  Bottom Layer w0.254: J60.3@65.737,173.399 J33.3@79.225,173.399 ; v1(79.68,163.703) 94.818,163.703 102.159,156.362 v1(105.004,156.362)
232_Rxd4: J31.3 J55.2 U23.13 | length 104.9
  Top Layer w0.254: J31.3@119.992,173.355 117.818,173.355 117.5,173.672 117.5,182.562 117.666,182.728 122.475,182.728 126.095,179.108 129.489,179.108 130.569,180.188 132.718,180.188 132.743,180.162 132.743,179.248 132.258,178.762 132.258,178.435 U23.13@131.549,178.435
  Bottom Layer w0.254: J55.2@51.839,182.474 62.863,171.45 107.823,171.45 109.728,173.355 J31.3@119.992,173.355
232_Txd2: D42.2 J33.1 J57.2 J60.1 U24.14 | length 99
  Top Layer w0.254: v1(78.181,164.694) 76.429,166.446 76.429,180.657 76.79,181.019 J33.1@79.225,181.019 79.225,187.401 78.588,188.038 J57.2@78.588,194.439 ; v1(85.115,177.317) 85.986,176.447 U24.14@90.401,176.447 ; v1(106.832,157.48) 106.832,156.337 107.62,155.55 107.62,150.368 D42.2@107.607,150.368
  Bottom Layer w0.254: J60.1@65.737,181.019 J33.1@79.225,181.019 81.414,181.019 v1(85.115,177.317) ; v1(78.181,164.694) 95.326,164.694 102.539,157.48 v1(106.832,157.48)
232_Txd4: J31.1 J55.3 U23.14 | length 83.1
  Top Layer w0.254: J31.1@119.992,180.975 122.123,180.975 125.4,177.698 127.965,177.698 128.499,177.165 U23.14@131.549,177.165
  Bottom Layer w0.254: J55.3@51.839,185.244 91.616,185.244 95.885,180.975 J31.1@119.992,180.975
485_A: J10.1 J11.1 R44.2 U14.6 U42.2 | length 58.9
  Top Layer w0.254: U14.6@181.358,70.858 183.82,70.858 ; v1(184.328,68.351) 184.328,70.35 ; R44.2@187.327,69.842 184.836,69.842 184.328,70.35 ; U42.2@192.66,69.594 197.467,64.787 J10.1@203.996,64.787 ; 183.82,70.858 183.955,70.858 184.328,70.485 184.328,70.35 ; 183.82,70.858 184.328,70.35
  Bottom Layer w0.254: v1(184.328,68.351) 187.892,64.787 J10.1@203.996,64.787 211.557,64.787 211.606,64.738 J11.1@219.19,64.738
485_A1: J14.1 J15.1 R45.2 U15.6 U16.2 | length 59
  Top Layer w0.254: v1(182.194,96.114) 183.667,97.587 183.667,101.871 183.642,101.897 U15.6@182.374,101.897 ; R45.2@187.581,101.389 189.916,101.389 190.071,101.234 U16.2@192.427,101.234 v1(192.427,97.13)
  Bottom Layer w0.254: v1(182.194,96.114) 184.514,93.794 195.763,93.794 ; v1(192.427,97.13) 195.763,93.794 ; J15.1@218.821,93.794 J14.1@203.962,93.794 195.763,93.794
485_B: J10.2 J11.2 R44.1 U14.7 U42.1 | length 55.1
  Top Layer w0.254: U14.7@181.358,72.128 186.373,72.128 ; v1(186.004,70.663) 186.004,71.76 186.373,72.128 ; R44.1@187.327,72.128 186.373,72.128 ; U42.1@192.64,71.654 193.751,70.543 193.751,69.156 194.31,68.597 J10.2@203.996,68.597
  Bottom Layer w0.254: v1(186.004,70.663) 188.07,68.597 J10.2@203.996,68.597 211.557,68.597 211.606,68.548 J11.2@219.19,68.548
485_B1: J14.2 J15.2 R45.1 U15.7 U16.1 | length 64.6
  Top Layer w0.254: U15.7@182.374,103.167 183.515,103.167 183.972,102.71 183.972,96.596 v1(183.54,96.164) ; v1(188.316,98.755) 186.766,100.305 186.766,103.53 186.911,103.675 R45.1@187.581,103.675 189.789,103.675 190.17,103.294 U16.1@192.407,103.294
  Bottom Layer w0.254: v1(183.54,96.164) 185.547,98.171 195.148,98.171 ; v1(188.316,98.755) 194.564,98.755 195.148,98.171 ; J15.2@218.821,97.604 J14.2@203.962,97.604 196.274,97.604 ; 195.148,98.171 195.715,97.604 196.274,97.604 ; 195.148,98.171 195.707,98.171 196.274,97.604
AD1: P5.8 U25.15 | length 50.1
  Top Layer w0.254: U25.15@88.92,58.563 85.608,58.563 83.363,56.318 83.363,29.909 86.36,26.912 86.36,24.854 86.677,24.536 94.935,24.536 P5.8@96.491,26.093
AD2: P5.10 U25.16 | length 46.1
  Top Layer w0.254: U25.16@88.92,58.063 85.787,58.063 83.668,55.944 83.668,51.613 84.607,50.673 84.607,29.274 86.677,27.204 86.677,25.159 86.995,24.841 92.699,24.841 P5.10@93.951,26.093
AD3: P5.12 U25.17 | length 42.1
  Top Layer w0.254: U25.17@88.92,57.563 85.897,57.563 83.972,55.639 83.972,51.918 85.877,50.013 85.877,28.613 86.995,27.496 86.995,25.463 87.312,25.146 90.464,25.146 P5.12@91.411,26.093
AD4: P5.14 U25.18 | length 36.1
  Top Layer w0.254: P5.14@88.871,26.093 86.182,28.782 86.182,50.317 84.277,52.222 84.277,54.663 86.677,57.063 U25.18@88.92,57.063
GND: C8.2 C12.2 C13.2 C17.2 C30.2 C33.2 C37.2 C45.2 C46.2 C48.2 C52.2 C73.2 C74.2 C75.2 C76.2 C77.2 C78.2 C80.2 C81.2 D9.1 J1.3 J2.3 J3.3 J4.3 J10.4 J11.4 J14.4 J15.4 J40.3 LED1.2 LED3.2 LED6.2 P2.2 P6.5 R24.1 U1.2 U2.2 U3.2 U4.2 U5.2 U6.2 U9.3 U10.3 U11.3 U12.3 U26.3 U26.5 | length 777
  Top Layer w1.5: P2.2@45.212,75.565 51.956,75.565 52.273,75.882 v1(52.273,100.113) ; LED1.2@65.244,139.445 71.477,139.445 71.806,139.116 74.004,139.116 C52.2@75.555,140.667 ; C13.2@78.222,117.172 79.202,118.152 C12.2@90.321,118.152 94.056,118.152 96.433,115.775 C8.2@101.125,115.775 101.125,123.386 100.569,123.942 U6.2@100.569,126.82 100.569,140.017 100.047,140.54 ; C48.2@83.683,136.73 87.62,140.667 C46.2@91.474,140.667 95.555,140.667 95.682,140.54 C45.2@96.935,140.54 100.047,140.54 ; C30.2@120.132,127.332 120.132,129.758 120.523,130.15 120.523,140.461 120.015,140.969 LED6.2@119.069,140.969 112.166,140.969 111.483,140.286 C33.2@110.778,140.286 108.636,140.286 108.382,140.54 C37.2@104.536,140.54 100.047,140.54 ; D9.1@130.431,103.442 130.431,105.41 130.787,105.766 137.135,105.766 137.16,105.74 143.514,105.74 143.844,105.41 U26.5@143.844,99.52 143.844,94.709 145.208,93.345 146.926,93.345 U26.3@147.244,93.662 ; U1.2@134.716,36.618 137.024,36.618 141.332,32.309 J1.3@141.332,28.396 ; C78.2@144.362,131.581 145.714,130.229 C75.2@155.878,130.229 ; U2.2@153.588,35.825 155.321,35.825 160.128,31.017 J2.3@160.128,28.015 ; C77.2@163.244,130.229 C75.2@155.878,130.229 ; J3.3@178.67,27.888 178.67,31.115 173.12,36.666 U3.2@171.8,36.666 166.052,36.666 165.1,37.618 165.1,72.555 165.545,73 R24.1@166.542,73 166.542,81.57 C81.2@161.038,87.074 159.417,88.695 U26.3@147.244,88.695 U26.3@147.244,93.662 ; C74.2@178.992,119.815 176.96,121.847 C73.2@176.96,129.744 175.26,129.744 174.934,130.069 LED3.2@174.934,145.202 178.318,145.202 178.435,145.085 U11.3@198.247,145.085 ; U4.2@188.818,37.349 189.484,37.349 189.484,30.886 189.465,30.868 J4.3@189.465,28.015 ; U9.3@196.088,198.357 196.088,184.963 198.044,183.007 U10.3@198.044,180.323 198.044,171.272 197.409,170.637 197.409,164.846 198.628,163.627 U12.3@198.628,161.876 198.628,160.147 197.028,158.547 197.028,147.599 198.247,146.38 U11.3@198.247,145.085 ; U11.3@198.247,144.649 U11.3@198.247,145.085 ; J14.4@203.962,105.224 206.375,105.224 206.807,104.792 206.807,76.649 206.375,76.217 ; J10.4@203.996,76.217 206.375,76.217 ; U5.2@208.249,36.666 208.229,36.666 208.229,30.632 208.261,30.6 J40.3@208.261,27.888 ; J11.4@219.19,76.168 206.805,76.168 206.756,76.217 206.375,76.217 ; U26.3@147.244,93.662 147.244,96.952 ; U26.3@147.244,93.662 147.244,96.952 ; 147.244,96.952 U26.3@147.244,99.52 147.244,108.768 C80.2@158.291,119.815 158.291,124.97 155.878,127.383 C75.2@155.878,130.229
  Bottom Layer w1.5: v1(52.273,100.113) C17.2@66.792,114.632 69.332,117.172 C13.2@78.222,117.172 ; C52.2@75.555,140.667 79.492,136.73 C48.2@83.683,136.73 ; P6.5@112.874,26.093 118.125,31.344 140.97,31.344 141.332,30.981 141.332,30.48 ; C30.2@120.132,127.332 124.381,131.581 C78.2@144.362,131.581 ; J1.3@141.332,28.396 141.332,30.48 ; C80.2@158.291,119.815 167.132,119.815 167.386,120.069 C76.2@168.705,120.069 168.732,120.096 168.732,120.88 177.927,120.88 C74.2@178.992,119.815 193.583,105.224 J14.4@203.962,105.224 J15.4@218.821,105.224 ; J2.3@160.128,28.015 160.128,30.233 ; J3.3@178.67,27.888 J3.3@178.67,28.015 ; J40.3@208.261,27.888 208.261,30.48 207.88,30.861 189.846,30.861 189.465,30.48 J4.3@189.465,28.015 J3.3@178.67,28.015 ; 141.332,30.48 141.688,30.836 159.773,30.836 160.128,30.48 160.128,30.233 ; 160.128,30.233 160.655,30.759 178.118,30.759 178.67,30.206 J3.3@178.67,28.015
